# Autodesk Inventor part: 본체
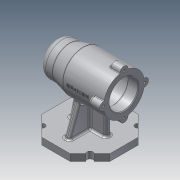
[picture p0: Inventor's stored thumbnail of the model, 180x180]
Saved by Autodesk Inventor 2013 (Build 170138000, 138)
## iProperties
Created: 2021-01
Part Number: 본체
Material: 알루미늄 6061
Document SubType Name: Modeling
Designer: a
Density: 2.71 g/cm^3
Mass: 631.974 g
Surface Area: 614.666 cm^2
Volume: 233.201 cm^3
Author: a
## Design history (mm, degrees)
sketch "스케치1"
  geometry: L1 (-50, 0)-(50, 0); L2 (50, 0)-(50, 30); L3 (50, 30)-(-10, 30); L4 (-10, 30)-(-30, 25); L5 (-30, 25)-(-50, 25); L6 (-50, 25)-(-50, 0); L7 (50, 21)-(35, 21); L8 (35, 21)-(35, 24); L9 (35, 24)-(-7, 24); L10 (-7, 24)-(-7, 21); L11 (-7, 21)-(-19, 21); L12 (-19, 21)-(-19, 17.5); L13 (-19, 17.5)-(-37, 17.5); L14 (-37, 17.5)-(-37, 16); L15 (-37, 16)-(-41, 16); L16 (-41, 16)-(-41, 10.5); L17 (-41, 10.5)-(-44, 10.5); L18 (-44, 10.5)-(-44, 0); 2 further points
  constraints: 36 end point, 10 parallel, 5 perpendicular, 2 point on line, 1 coincident, 1 collinear, 1 horizontal, 1 midpoint
  dimensions: "d0" = 100 distance of L1.start L1.end; "d1" = 40 horizontal distance of L3.end L1.start; "d2" = 20 horizontal distance of L1.start L4.end; "d3" = 60 diameter of L3 L1; "d4" = 50 diameter of L5 L1; "d5" = 42 diameter of L7 L1; "d6" = 42 diameter of L11 L1; "d7" = 48 diameter of L9 L1; "d8" = 35 diameter of L13 L1; "d9" = 32 diameter of L15 L1; "d10" = 21 diameter of L17 L1; "d11" = 15 distance of L7.start L7.end; "d12" = 42 distance of L8.end L9.end; "d13" = 18 distance of L12.end L13.end; "d14" = 12 distance of L10.end L11.end; "d15" = 4 distance of L14.end L15.end; "d16" = 3 distance of L16.end L17.end
revolve "회전1" sketch "스케치1" stored, may be unused: angle "d17" = 90 deg
fillet "모깎기1" dims "d18" = 3
fillet "모깎기2" dims "d19" = 0.3
chamfer "모따기1" distance "d20" = 1; stored, may be unused: second distance "d21" = 2, angle "d22" = 45 deg
fillet "모깎기3" dims "d23" = 10
node "작업 평면1"
sketch "스케치2"
  geometry: L1 (-20.711, -50)-(-50, -20.711); L2 (-50, -20.711)-(-50, 20.711); L3 (-50, 20.711)-(-20.711, 50); L4 (-20.711, 50)-(20.711, 50); L5 (20.711, 50)-(50, 20.711); L6 (50, 20.711)-(50, -20.711); L7 (50, -20.711)-(20.711, -50); L8 (20.711, -50)-(-20.711, -50); 3 further points
  constraints: 16 end point, 1 coincident, 1 midpoint, 1 vertical alignment, 17 other
  dimensions: "d25" = 50 distance from line of L2 point (0, 0)
extrude "돌출1" join sketch "스케치2" distance "d26" = 10; taper "d27" = 0 deg
sketch "스케치3"
  geometry: L1 (20.711, 50)-(-20.711, 50) reference; L2 (-20.711, 50)-(-50, 20.711) reference; L3 (20.711, -50)-(50, -20.711) reference; L4 (0, 0)-(0, 50); L5 (0, 0)-(-35.355, 35.355); C1 r 4.5 at (-35.355, 35.355)
  constraints: 4 end point, 2 midpoint, 1 centre point, 1 coincident, 1 perpendicular
  dimensions: "d29" = 9 diameter of C1
extrude "돌출2" cut sketch "스케치3" stored distance "d30" = 10; taper "d31" = 0 deg
sketch "스케치4"
  geometry: L1 (27, -4)-(-27, -4); L2 (-27, -4)-(-27, 4); L3 (-27, 4)-(27, 4); L4 (27, 4)-(27, -4); L5 (27, -4)-(-27, 4); L6 (-27, -4)-(27, 4); 1 further point
  constraints: 12 end point, 2 midpoint, 2 parallel, 1 horizontal, 1 perpendicular
  dimensions: "d35" = 54 distance of L2.end L3.end; "d36" = 8 distance of L3.end L1.start
extrude "돌출3" join sketch "스케치4" stored distance "d37" = 10; taper "d38" = 0 deg
feature "면 기울기1" dims angle "d39" = 11 deg
sketch "스케치6"
  geometry: L1 (-75, -50)-(-75, 50) reference; L2 (-75, 50)-(-65, 50) reference; L3 (-65, 50)-(-65, 4) reference; L4 (-65, 4)-(-29.732, 4) reference; L5 (-29.732, -4)-(-65, -4) reference; L6 (-65, -4)-(-65, -50) reference; L7 (-65, -50)-(-75, -50) reference; L8 (-22.707, 19.606)-(-65, 35); C1 r 24 at (0, 0) reference; A1 r 30 centre (0, 0) between (-29.732, -4) and (-29.732, 4) reference; 1 further point
  constraints: 2 end point, 1 point on circle, 1 point on line
  dimensions: "d40" = 110 deg angle of L3 L8; "d41" = 15 distance from line of L8.end L2
feature "리브1" sketch "스케치6" dims "d42" = 1, "d43" = 8, "d44" = 0, "d45" = 0, "d46" = 1, "d47" = 1
sketch "스케치7"
  geometry: C1 r 6 at (0, 30); 1 further point
  constraints: 2 vertical alignment, 1 centre point, 1 other
  dimensions: "d48" = 12 diameter of C1
extrude "돌출4" join sketch "스케치7" distance "d49" = 16; taper "d50" = 0 deg
fillet "모깎기4" dims "d51" = 3
fillet "모깎기5" dims "d52" = 1
sketch "스케치8"
  geometry: A1 r 6 centre (0, 0) between (5.998, 0.171) and (-5.998, 0.171) reference; 1 further point
  constraints: 1 coincident
hole "구멍1" sketch "스케치8" at (0, 0) diameter "d53" = 3.242; stored, may be unused: countersink angle "d57" = 90 deg, drill point angle "d59" = 118 deg; dims "d54" = 8, "d55" = 4, "d56" = 2, "d58" = 10
fillet "모깎기6" dims "d63" = 3
fillet "모깎기7" dims "d64" = 3
fillet "모깎기8" dims "d65" = 3
node "작업 평면2"
sketch "스케치9"
  geometry: L1 (50, 6.771)-(50, 29.226) reference; 2 further points
  constraints: 1 horizontal alignment, 1 other
  dimensions: "d67" = 38 distance from line of L1 point (12, 0)
feature "엠보싱1" sketch "스케치9" dims "d68" = 0.5, "d69" = 0
fillet "모깎기9" dims "d70" = 3
node "솔리드1"
pattern_circular "원형 패턴1" dims angle "d33" = 360 deg
mirror "대칭1"
pattern_circular "원형 패턴2" dims "d61" = 360 deg
node "절단 모서리 투영1"
other parameters: "d24" = -75, "d66" = 37.5
